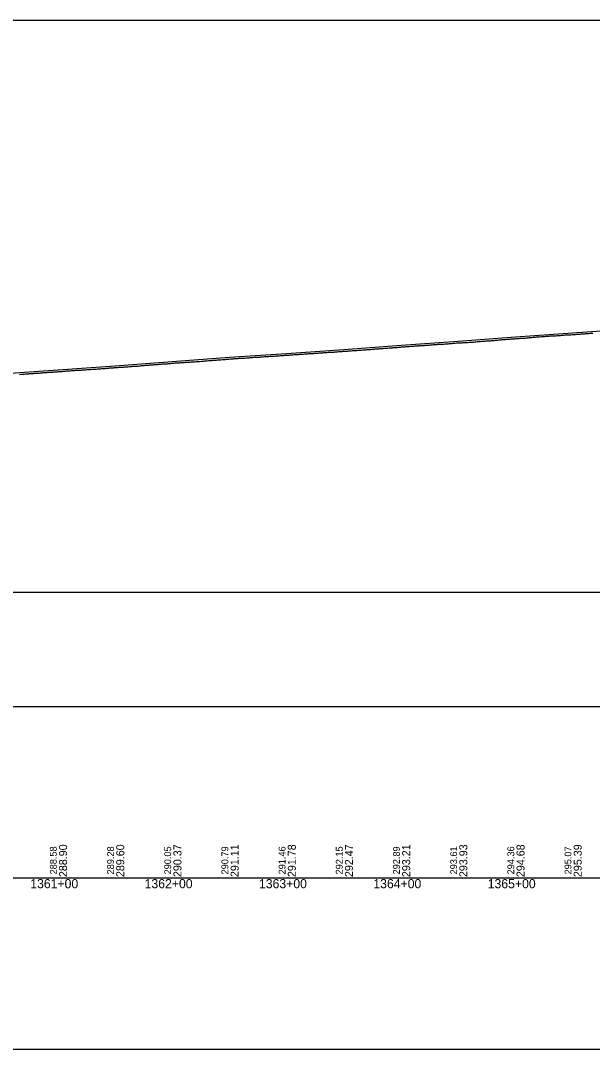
# Model space of a CAD drawing. Extents: x -3627 to 47473, y 2850 to 4350.
# Drawn here: x 23545 to 24045, y 2850 to 3750 of the extents above; entities that cross this region are included whole.
import ezdxf

# ---------------------------------------------------------------- set-up
doc = ezdxf.new("R2010")
doc.units = 0
for name, color, linetype in [('RD_DDB_Profile_EX', 7, 'Continuous'), ('RD_DDB_Profile_PR', 7, 'Continuous'), ('RD_DDB_StaTX', 7, 'Continuous'), ('RD_DDB_StripGrade', 7, 'Continuous'), ('RD_GPK_Profile_Cell', 7, 'Continuous'), ('RD_SHT_ShtClip', 7, 'Continuous')]:
    doc.layers.add(name, color=color, linetype=linetype)

msp = doc.modelspace()

# ---------------------------------------------------------------- linework, layer by layer
at = {"layer": 'RD_DDB_Profile_EX'}
for points in [[(23986.789877, 3472.3344), (23987.783354, 3472.43457), (23988.784251, 3472.578965), (23989.782704, 3472.721305), (23990.783604, 3472.772345), (23991.781613, 3472.87089), (23992.783644, 3472.958875), (23993.78455, 3473.05343), (23994.782556, 3473.101825), (23995.784589, 3473.20967), (23996.782596, 3473.25813), (23997.783503, 3473.34607), (23998.785537, 3473.49085), (23999.783542, 3473.58257), (24000.784454, 3473.63381), (24001.783581, 3473.682225), (24002.784491, 3473.74002), (24003.777966, 3473.79023), (24004.783845, 3473.883405), (24005.784765, 3473.9781), (24006.782755, 3474.032915), (24007.7848, 3474.121205), (24008.782791, 3474.21281), (24009.783713, 3474.21413), (24010.778311, 3474.2449), (24011.783748, 3474.324385), (24012.784675, 3474.36507), (24013.783783, 3474.45682), (24014.784708, 3474.45816), (24015.778183, 3474.54533), (24016.784741, 3474.651235), (24017.937309, 3474.732205), (24018.935052, 3474.73652), (24019.928514, 3474.86843), (24020.93029, 3474.95783), (24021.931482, 3474.985575), (24022.933265, 3475.081305), (24023.934474, 3475.12127), (24024.928494, 3475.184405), (24025.930275, 3475.242525), (24026.931493, 3475.344775), (24027.933279, 3475.396685), (24028.934512, 3475.442925), (24029.936305, 3475.48892), (24030.929734, 3475.58404), (24031.927429, 3475.705925), (24032.928682, 3475.66383), (24033.930474, 3475.804185), (24034.932266, 3475.889025), (24035.925675, 3475.990025), (24036.927465, 3476.064425), (24037.92874, 3476.105375), (24038.930535, 3476.168265), (24039.931825, 3476.22577), (24040.933626, 3476.227475), (24041.927019, 3476.283705), (24042.928817, 3476.419245), (24043.926477, 3476.46274), (24044.927789, 3476.48574)], [(23786.832453, 3457.891355), (23787.832926, 3457.933695), (23788.826513, 3458.0751), (23789.831508, 3458.13358), (23790.832002, 3458.193935), (23791.834985, 3458.286165), (23792.828569, 3458.336555), (23793.82907, 3458.446775), (23794.829584, 3458.53054), (23795.831067, 3458.57281), (23796.824643, 3458.673215), (23797.82663, 3458.683575), (23798.827163, 3458.69359), (23799.826219, 3458.791665), (23800.826753, 3458.85164), (23801.827298, 3458.944365), (23802.820866, 3459.053275), (23803.827394, 3459.135815), (23804.828882, 3459.17827), (23805.822448, 3459.237165), (23806.823008, 3459.305465), (23807.82358, 3459.35673), (23808.8226, 3459.446425), (23809.824593, 3459.53952), (23810.825169, 3459.540885), (23811.818727, 3459.599585), (23812.820219, 3459.67558), (23813.825351, 3459.79996), (23814.820312, 3459.842175), (23815.820902, 3459.893515), (23816.821503, 3459.911265), (23817.8205, 3460.00947), (23818.821101, 3460.060695), (23819.821714, 3460.137385), (23820.816643, 3460.20424), (23821.81814, 3460.305155), (23822.822817, 3460.404055), (23823.817654, 3460.444915), (23824.818663, 3460.511675), (23825.819673, 3460.603855), (23826.819063, 3460.70107), (23827.820066, 3460.751435), (23828.82197, 3460.793165), (23829.815932, 3460.875945), (23830.816934, 3460.90121), (23831.824786, 3460.99119), (23832.818761, 3461.065425), (23833.82067, 3461.157035), (23834.821663, 3461.257655), (23835.820189, 3461.28834), (23836.822102, 3461.329855), (23837.823091, 3461.44715), (23838.818009, 3461.53765), (23839.818993, 3461.59651), (23840.824517, 3461.694975), (23841.819454, 3461.73537), (23842.820433, 3461.785745), (23843.819926, 3461.83268), (23844.820898, 3461.95041), (23845.819444, 3462.04796), (23846.821374, 3462.10669), (23847.82234, 3462.198245), (23848.821861, 3462.24538), (23849.82282, 3462.29571), (23850.822359, 3462.37481), (23851.823311, 3462.49315), (23852.817367, 3462.565445), (23853.823814, 3462.640565), (23854.82476, 3462.74998), (23855.824328, 3462.797175), (23856.825267, 3462.856685), (23857.819347, 3462.90608), (23858.825786, 3463.04495), (23859.81988, 3463.13496), (23860.827902, 3463.17376), (23861.828826, 3463.28349), (23862.822935, 3463.34226), (23863.827284, 3463.360155), (23864.821946, 3463.45065), (23865.827879, 3463.58076), (23866.822548, 3463.640285), (23867.824014, 3463.74121), (23868.828901, 3463.800275), (23869.823566, 3463.87173), (23870.829498, 3463.901695), (23871.822564, 3463.982305), (23872.824036, 3464.11203), (23873.823166, 3464.11961), (23874.824636, 3464.19928), (23875.829507, 3464.289285), (23876.824183, 3464.38928), (23877.825655, 3464.471115), (23878.823168, 3464.509325), (23879.824645, 3464.619945), (23880.826122, 3464.73048), (23881.825245, 3464.75939), (23882.825666, 3464.851325), (23883.82034, 3464.939575), (23884.826263, 3465.01953), (23885.827739, 3465.041825), (23886.820804, 3465.13198)], [(23886.820804, 3465.13198), (23887.826721, 3465.20974), (23888.821403, 3465.319345), (23889.821826, 3465.42077), (23890.827743, 3465.47945), (23891.822421, 3465.569855), (23892.823898, 3465.61128), (23893.821401, 3465.64943), (23894.822882, 3465.690885), (23895.823315, 3465.811555), (23896.822422, 3465.79998), (23897.823904, 3465.910605), (23898.81858, 3466.010595), (23899.823444, 3466.0985), (23900.82549, 3466.13087), (23901.81807, 3466.203225), (23902.823513, 3466.34137), (23903.817694, 3466.39235), (23904.818708, 3466.475485), (23905.822595, 3466.575435), (23906.816773, 3466.635785), (23907.817814, 3466.669205), (23908.816419, 3466.77765), (23909.817466, 3466.820405), (23910.816982, 3466.84041), (23911.815577, 3466.92136), (23912.81665, 3467.005195), (23913.810802, 3467.065305), (23914.814795, 3467.07424), (23915.815892, 3467.14931), (23916.814476, 3467.19838), (23917.815578, 3467.291595), (23918.809723, 3467.351575), (23919.813764, 3467.46033), (23920.81489, 3467.529945), (23921.80903, 3467.66334), (23922.814592, 3467.730945), (23923.814253, 3467.79127), (23924.808389, 3467.892135), (23925.809536, 3467.993855), (23926.81069, 3468.00408), (23927.810414, 3468.06399), (23928.804527, 3468.081585), (23929.805697, 3468.124625), (23930.807759, 3468.2009), (23931.808934, 3468.28609), (23932.801622, 3468.294955), (23933.802807, 3468.380375), (23934.803998, 3468.457985), (23935.805194, 3468.50198), (23936.797896, 3468.560705), (23937.799102, 3468.662675), (23938.800314, 3468.656785), (23939.801034, 3468.6926), (23940.795073, 3468.793575), (23941.7958, 3468.918245), (23942.797843, 3469.012115), (23943.798582, 3469.1364), (23944.799331, 3469.18007), (23945.79415, 3469.253245), (23946.794101, 3469.332175), (23947.794866, 3469.45586), (23948.796904, 3469.49975), (23949.790425, 3469.550005), (23950.792453, 3469.664565), (23951.79323, 3469.75865), (23952.793248, 3469.839495), (23953.787995, 3469.93268), (23954.788788, 3469.89838), (23955.794114, 3469.95497), (23956.796147, 3470.02781), (23957.789654, 3470.11369), (23958.790924, 3470.20812), (23959.791741, 3470.33046), (23960.792567, 3470.37445), (23961.794593, 3470.475645), (23962.788088, 3470.618885), (23963.788924, 3470.626895), (23964.790217, 3470.771465), (23965.791069, 3470.872545), (23966.785718, 3470.9297), (23967.786571, 3471.01719), (23968.787432, 3471.11157), (23969.789443, 3471.182915), (23970.782217, 3471.320015), (23971.787647, 3471.389455), (23972.782266, 3471.45311), (23973.783139, 3471.67745), (23974.789711, 3471.72033), (23975.783187, 3471.72717), (23976.787921, 3471.733485), (23977.782535, 3471.83379), (23978.783418, 3471.87157), (23979.781445, 3471.9334), (23980.783463, 3472.021275), (23981.788898, 3472.077305), (23982.782376, 3472.12749), (23983.784395, 3472.22864), (23984.78242, 3472.23386), (23985.783311, 3472.28484), (23986.789877, 3472.3344)], [(23686.846328, 3450.8528), (23687.848295, 3451.033875), (23688.843471, 3451.083535), (23689.848884, 3451.14261), (23690.849252, 3451.23293), (23691.844456, 3451.28258), (23692.845364, 3451.32305), (23693.845075, 3451.41222), (23694.84706, 3451.471915), (23695.84796, 3451.531765), (23696.8477, 3451.620925), (23697.849694, 3451.72086), (23698.850584, 3451.770955), (23699.849793, 3451.82028), (23700.849571, 3451.870545), (23701.844307, 3451.88048), (23702.849108, 3452.09054), (23703.850558, 3452.131115), (23704.84529, 3452.07074), (23705.851201, 3452.34058), (23706.844273, 3452.39046), (23707.84572, 3452.450855), (23708.851627, 3452.57059), (23709.846366, 3452.62059), (23710.847811, 3452.67116), (23711.845342, 3452.75993), (23712.846791, 3452.80058), (23713.848241, 3452.881395), (23714.847438, 3452.93998), (23715.848885, 3453.01059), (23716.848669, 3453.101125), (23717.847857, 3453.18987), (23718.848204, 3453.240895), (23719.842942, 3453.33095), (23720.848843, 3453.43028), (23721.848628, 3453.49078), (23722.843367, 3453.59078), (23723.849263, 3453.63016), (23724.844009, 3453.690155), (23725.84546, 3453.820945), (23726.84525, 3453.921525), (23727.844429, 3453.96005), (23728.845885, 3454.030775), (23729.847342, 3454.15177), (23730.846524, 3454.190135), (23731.847979, 3454.260935), (23732.841049, 3454.310735), (23733.846944, 3454.359995), (23734.847302, 3454.46119), (23735.842039, 3454.56119), (23736.847934, 3454.600475), (23737.841003, 3454.650265), (23738.842464, 3454.721), (23739.848354, 3454.770305), (23740.843098, 3454.820305), (23741.844557, 3454.941245), (23742.842055, 3454.95939), (23743.843518, 3455.060195), (23744.844981, 3455.110995), (23745.844153, 3455.159465), (23746.845614, 3455.25028), (23747.845404, 3455.381), (23748.844567, 3455.429235), (23749.846033, 3455.44015), (23750.840779, 3455.450145), (23751.842238, 3455.550985), (23752.84645, 3455.59001), (23753.841198, 3455.68001), (23754.842661, 3455.78093), (23755.844124, 3455.84177), (23756.838857, 3455.901685), (23757.841985, 3456.00111), (23758.843458, 3456.05194), (23759.84493, 3456.102775), (23760.839654, 3456.192915), (23761.84112, 3456.223245), (23762.840941, 3456.354235), (23763.842413, 3456.364815), (23764.837118, 3456.414815), (23765.838584, 3456.515605), (23766.840049, 3456.537405), (23767.839897, 3456.62847), (23768.834582, 3456.788095), (23769.836048, 3456.78901), (23770.837513, 3456.799475), (23771.838979, 3456.89084), (23772.832046, 3456.990615), (23773.83798, 3457.030205), (23774.83945, 3457.11213), (23775.84092, 3457.19159), (23776.835579, 3457.25105), (23777.837042, 3457.361355), (23778.836926, 3457.40259), (23779.838396, 3457.444105), (23780.833036, 3457.53473), (23781.833471, 3457.57681), (23782.834938, 3457.677805), (23783.835391, 3457.779235), (23784.828989, 3457.838835), (23785.830986, 3457.89041), (23786.832453, 3457.891355)], [(23586.853705, 3443.55114), (23587.856203, 3443.68293), (23588.85612, 3443.77048), (23589.85522, 3443.810065), (23590.856154, 3443.869575), (23591.857089, 3443.96975), (23592.859589, 3444.07006), (23593.853677, 3444.160365), (23594.85461, 3444.24197), (23595.855545, 3444.223625), (23596.855682, 3444.22179), (23597.856611, 3444.322035), (23598.857541, 3444.412925), (23599.858473, 3444.43516), (23600.854141, 3444.55345), (23601.855069, 3444.60372), (23602.856, 3444.725995), (23603.856931, 3444.726305), (23604.859429, 3444.804745), (23605.853524, 3444.8728), (23606.854454, 3444.923055), (23607.855385, 3445.014005), (23608.857878, 3445.07374), (23609.851974, 3445.1232), (23610.852904, 3445.17345), (23611.855392, 3445.26462), (23612.856323, 3445.30564), (23613.850419, 3445.3736), (23614.851349, 3445.47386), (23615.853832, 3445.515055), (23616.854763, 3445.6061), (23617.855695, 3445.72483), (23618.84979, 3445.783525), (23619.852268, 3445.874725), (23620.853198, 3445.902625), (23621.854131, 3446.00285), (23622.848226, 3446.093155), (23623.850699, 3446.161965), (23624.851629, 3446.25299), (23625.852561, 3446.294045), (23626.846656, 3446.384335), (23627.849124, 3446.443955), (23628.849546, 3446.48148), (23629.849981, 3446.59134), (23630.843562, 3446.723475), (23631.845512, 3446.87447), (23632.845964, 3446.92533), (23633.847413, 3446.852515), (23634.840983, 3446.91732), (23635.842923, 3447.044695), (23636.847979, 3447.094415), (23637.841547, 3447.153395), (23638.84203, 3447.24533), (23639.848059, 3447.386075), (23640.843094, 3447.510195), (23641.843581, 3447.51982), (23642.841724, 3447.568825), (23643.84222, 3447.611025), (23644.842729, 3447.687845), (23645.842316, 3447.787105), (23646.843778, 3447.74628), (23647.841912, 3447.804205), (23648.842422, 3448.02024), (23649.842944, 3448.10392), (23650.842517, 3448.17891), (23651.843039, 3448.27112), (23652.83755, 3448.379695), (23653.842634, 3448.42937), (23654.844608, 3448.463185), (23655.83817, 3448.58782), (23656.843265, 3448.6545), (23657.836829, 3448.7633), (23658.838307, 3448.863935), (23659.84484, 3448.897775), (23660.838402, 3448.98945), (23661.838951, 3449.04017), (23662.844059, 3449.115285), (23663.838548, 3449.198325), (23664.839535, 3449.24851), (23665.839011, 3449.355645), (23666.84093, 3449.47279), (23667.841909, 3449.51436), (23668.841409, 3449.639205), (23669.843334, 3449.697875), (23670.835891, 3449.7215), (23671.842349, 3449.77957), (23672.84428, 3449.864775), (23673.838315, 3450.005835), (23674.844774, 3450.08759), (23675.83981, 3450.128315), (23676.840762, 3450.205265), (23677.847223, 3450.259695), (23678.842289, 3450.30924), (23679.843233, 3450.46844), (23680.841296, 3450.52641), (23681.843249, 3450.59478), (23682.845202, 3450.61713), (23683.843799, 3450.706815), (23684.845759, 3450.82541), (23685.847719, 3450.84403), (23686.846328, 3450.8528)], [(23543.860487, 3440.516725), (23544.865339, 3440.56637), (23545.866817, 3440.66713), (23546.861501, 3440.717125), (23547.867417, 3440.816415), (23548.862108, 3440.86641), (23549.861958, 3440.986255), (23550.86787, 3440.99529), (23551.862561, 3441.08562), (23552.864035, 3441.145925), (23553.861535, 3441.19454), (23554.863013, 3441.27582), (23555.864491, 3441.407265), (23556.859177, 3441.43617), (23557.864527, 3441.515665), (23558.866005, 3441.61642), (23559.860696, 3441.666415), (23560.862167, 3441.6883), (23561.862025, 3441.76978), (23562.863503, 3441.83029), (23563.858175, 3441.928045), (23564.8641, 3442.0082), (23565.863967, 3442.108805), (23566.85864, 3442.149235), (23567.860116, 3442.202465), (23568.861591, 3442.3009), (23569.854657, 3442.422225), (23570.860584, 3442.449915), (23571.862063, 3442.44126), (23572.864582, 3442.55387), (23573.857648, 3442.66995), (23574.859123, 3442.761265), (23575.860599, 3442.81206), (23576.855245, 3442.86205), (23577.8596, 3442.980005), (23578.86108, 3443.040125), (23579.855727, 3443.08071), (23580.855624, 3443.168755), (23581.857104, 3443.209975), (23582.858583, 3443.36057), (23583.857686, 3443.41878), (23584.857591, 3443.469205), (23585.859075, 3443.510455), (23586.853705, 3443.55114)]]:
    msp.add_lwpolyline(points, dxfattribs=at)
at = {"layer": 'RD_DDB_Profile_PR'}
msp.add_lwpolyline([(23187.09, 3416.824774), (23227.33, 3419.252), (23277.33, 3422.747), (23327.33, 3426.709), (23377.33, 3430.136), (23427.33, 3433.627), (23477.33, 3437.1435), (23527.33, 3440.8465), (23577.33, 3444.518), (23627.33, 3448.013), (23677.33, 3451.8315), (23727.33, 3455.54), (23777.33, 3458.9055), (23827.33, 3462.327), (23877.33, 3466.0305), (23927.33, 3469.635), (23977.33, 3473.388), (24027.33, 3476.9655), (24077.33, 3480.2905)], dxfattribs=at)
at = {"layer": 'RD_GPK_Profile_Cell'}
msp.add_line((1000, 3000), (46705.077602, 3000), dxfattribs=at)
at = {"layer": 'RD_SHT_ShtClip'}
for points in [[(23453.33, 3750), (23453.33, 3250), (24953.33, 3250), (24953.33, 3250), (24953.33, 3750), (24953.33, 3750)], [(23433.33, 3150), (24973.33, 3150), (24973.33, 2850), (23433.33, 2850)]]:
    msp.add_lwpolyline(points, close=True, dxfattribs=at)

# ---------------------------------------------------------------- texts
at = {"layer": 'RD_DDB_StaTX'}
for s, p in [('1361+00', (23553.125471, 2991)), ('1362+00', (23653.125471, 2991)), ('1363+00', (23753.125471, 2991)), ('1364+00', (23853.125471, 2991)), ('1365+00', (23953.125471, 2991))]:
    msp.add_text(s, height=8, dxfattribs=at).set_placement(p)
at = {"layer": 'RD_DDB_StripGrade'}
for s, height, p in [('288.58', 6, (23576.33, 3003.073688)), ('288.90', 7, (23585.33, 3000.75)), ('289.28', 6, (23626.33, 3003.073688)), ('289.60', 7, (23635.33, 3000.75)), ('290.05', 6, (23676.33, 3003.073688)), ('290.37', 7, (23685.33, 3000.75)), ('290.79', 6, (23726.33, 3003.073688)), ('291.11', 7, (23735.33, 3000.75)), ('291.46', 6, (23776.33, 3003.073688)), ('291.78', 7, (23785.33, 3000.75)), ('292.15', 6, (23826.33, 3003.073688)), ('292.47', 7, (23835.33, 3000.75)), ('292.89', 6, (23876.33, 3003.073688)), ('293.21', 7, (23885.33, 3000.75)), ('293.61', 6, (23926.33, 3003.073688)), ('293.93', 7, (23935.33, 3000.75)), ('294.36', 6, (23976.33, 3003.073688)), ('294.68', 7, (23985.33, 3000.75)), ('295.07', 6, (24026.33, 3003.073688)), ('295.39', 7, (24035.33, 3000.75))]:
    msp.add_text(s, height=height, rotation=90, dxfattribs=at).set_placement(p)

doc.saveas('drawing.dxf')
